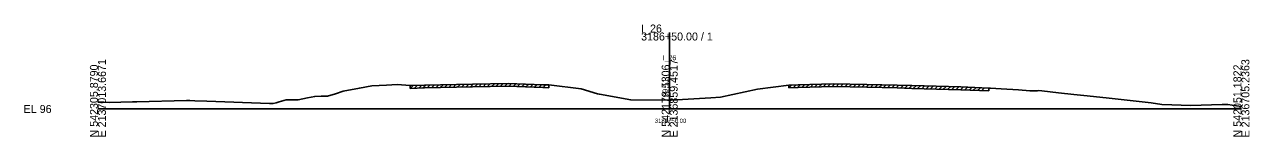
# Model space of a CAD drawing. Extents: x -13101 to 4803, y -924 to 22390.
# Drawn here: x 974.3 to 1402.8, y 12490.3 to 12529.7 of the extents above; entities that cross this region are included whole.
import ezdxf

# ---------------------------------------------------------------- set-up
doc = ezdxf.new("R2010")
doc.units = 0
for name, color, linetype in [('RD_GPK_XS_Cell', 7, 'Continuous'), ('RD_XS_ExGround', 7, 'Continuous'), ('RD_XS_ExPaveRet', 7, 'Continuous'), ('RD_XS_TX_Baseline', 7, 'Continuous'), ('RD_XS_TX_Elev_EX', 7, 'Continuous'), ('RD_XS_TX_Station', 7, 'Continuous')]:
    doc.layers.add(name, color=color, linetype=linetype)

msp = doc.modelspace()

# ---------------------------------------------------------------- linework, layer by layer
at = {"layer": 'RD_GPK_XS_Cell'}
for p, q in [((1200, 12500), (1200, 12526.84)), ((1000, 12500), (1200, 12500)), ((1200, 12500), (1400, 12500))]:
    msp.add_line(p, q, dxfattribs=at)
at = {"layer": 'RD_XS_ExGround'}
msp.add_lwpolyline([(1000, 12502.34), (1002.09, 12502.4), (1003.94, 12502.32), (1012.09, 12502.48), (1013.57, 12502.56), (1030.94, 12502.94), (1032.1, 12502.97), (1033.88, 12502.88), (1038.13, 12502.75), (1060.05, 12501.97), (1061.3, 12501.93), (1062.31, 12502.19), (1063.39, 12502.51), (1065.81, 12503.19), (1067.4, 12503.2), (1070.03, 12503.25), (1073.33, 12503.92), (1075.82, 12504.42), (1078.1, 12504.46), (1080.34, 12504.5), (1083.16, 12505.36), (1085.83, 12506.23), (1091.48, 12507.32), (1095.83, 12508.13), (1100.98, 12508.38), (1104.71, 12508.55), (1109.21, 12508.2), (1114.23, 12508.4), (1131.04, 12508.72), (1143.47, 12508.95), (1155.67, 12508.51), (1157.76, 12508.47), (1169.07, 12507.03), (1174.78, 12505.36), (1175.43, 12505.19), (1186.36, 12503.2), (1200, 12503.11), (1200.48, 12503.11), (1214.43, 12503.91), (1217.8, 12504.18), (1230.77, 12507), (1241.72, 12508.38), (1244.9, 12508.53), (1257.25, 12508.85), (1268.93, 12508.6), (1279.63, 12508.37), (1284.68, 12508.19), (1301.85, 12507.74), (1311.66, 12507.33), (1312.23, 12507.3), (1315.98, 12507.11), (1322.02, 12506.68), (1325.98, 12506.38), (1328.65, 12506.42), (1329.11, 12506.44), (1330.19, 12506.31), (1335.99, 12505.64), (1341.38, 12505.13), (1346, 12504.67), (1353.74, 12503.76), (1362.17, 12502.88), (1368.39, 12502.1), (1372.17, 12501.55), (1375.72, 12501.42), (1382.17, 12501.18), (1393.22, 12501.6), (1395.29, 12501.58), (1398.35, 12501.1), (1400, 12500.9)], dxfattribs=at)
at = {"layer": 'RD_XS_ExPaveRet'}
for p, q in [((1139.21, 12507.87), (1140.23, 12508.89)), ((1140.71, 12507.9), (1141.73, 12508.92)), ((1142.21, 12507.92), (1143.23, 12508.94)), ((1143.71, 12507.94), (1144.68, 12508.9)), ((1109.21, 12507.2), (1110.25, 12508.24)), ((1109.21, 12507.2), (1109.21, 12508.2)), ((1109.21, 12507.2), (1114.23, 12507.4)), ((1110.71, 12507.26), (1111.75, 12508.3)), ((1112.21, 12507.32), (1113.25, 12508.36)), ((1113.71, 12507.38), (1114.74, 12508.41)), ((1114.23, 12507.4), (1131.04, 12507.72)), ((1115.21, 12507.42), (1116.23, 12508.44)), ((1116.71, 12507.45), (1117.73, 12508.47)), ((1118.21, 12507.47), (1119.23, 12508.49)), ((1119.71, 12507.5), (1120.73, 12508.52)), ((1121.21, 12507.53), (1122.23, 12508.55)), ((1122.71, 12507.56), (1123.73, 12508.58)), ((1124.21, 12507.59), (1125.23, 12508.61)), ((1125.71, 12507.62), (1126.73, 12508.64)), ((1127.21, 12507.65), (1128.23, 12508.67)), ((1128.71, 12507.68), (1129.73, 12508.7)), ((1130.21, 12507.71), (1131.23, 12508.73)), ((1131.04, 12507.72), (1143.47, 12507.95)), ((1131.71, 12507.73), (1132.73, 12508.75)), ((1133.21, 12507.76), (1134.23, 12508.78)), ((1134.71, 12507.79), (1135.73, 12508.81)), ((1136.21, 12507.82), (1137.23, 12508.83)), ((1137.71, 12507.84), (1138.73, 12508.86)), ((1143.47, 12507.95), (1155.67, 12507.51)), ((1145.21, 12507.89), (1146.18, 12508.85)), ((1146.71, 12507.83), (1147.68, 12508.8)), ((1148.21, 12507.78), (1149.18, 12508.74)), ((1149.71, 12507.73), (1150.68, 12508.69)), ((1151.21, 12507.67), (1152.18, 12508.64)), ((1152.71, 12507.62), (1153.68, 12508.59)), ((1154.21, 12507.57), (1155.18, 12508.53)), ((1155.67, 12507.51), (1157.76, 12507.47)), ((1155.71, 12507.51), (1156.69, 12508.49)), ((1157.76, 12508.47), (1157.76, 12507.47)), ((1241.72, 12507.38), (1242.77, 12508.43)), ((1241.72, 12507.38), (1241.72, 12508.38)), ((1241.72, 12507.38), (1244.9, 12507.53)), ((1243.22, 12507.45), (1244.27, 12508.5)), ((1244.72, 12507.53), (1245.75, 12508.55)), ((1244.9, 12507.53), (1257.25, 12507.85)), ((1246.22, 12507.57), (1247.25, 12508.59)), ((1247.72, 12507.6), (1248.75, 12508.63)), ((1249.22, 12507.64), (1250.25, 12508.67)), ((1250.72, 12507.68), (1251.75, 12508.71)), ((1252.22, 12507.72), (1253.25, 12508.74)), ((1253.72, 12507.76), (1254.75, 12508.78)), ((1255.22, 12507.79), (1256.25, 12508.82)), ((1256.72, 12507.83), (1257.73, 12508.84)), ((1257.25, 12507.85), (1268.93, 12507.6)), ((1258.22, 12507.83), (1259.2, 12508.8)), ((1259.72, 12507.79), (1260.7, 12508.77)), ((1261.22, 12507.76), (1262.2, 12508.74)), ((1262.72, 12507.73), (1263.7, 12508.71)), ((1264.22, 12507.7), (1265.2, 12508.68)), ((1265.72, 12507.67), (1266.7, 12508.65)), ((1267.22, 12507.63), (1268.2, 12508.61)), ((1268.72, 12507.6), (1269.7, 12508.58)), ((1268.93, 12507.6), (1279.63, 12507.37)), ((1270.22, 12507.57), (1271.2, 12508.55)), ((1271.72, 12507.54), (1272.7, 12508.52)), ((1273.22, 12507.51), (1274.2, 12508.48)), ((1274.72, 12507.47), (1275.7, 12508.45)), ((1276.22, 12507.44), (1277.2, 12508.42)), ((1277.72, 12507.41), (1278.7, 12508.39)), ((1279.22, 12507.37), (1280.19, 12508.35)), ((1279.63, 12507.37), (1284.68, 12507.19)), ((1280.72, 12507.33), (1281.69, 12508.29)), ((1282.22, 12507.27), (1283.19, 12508.24)), ((1283.72, 12507.22), (1284.69, 12508.19)), ((1284.68, 12507.19), (1301.85, 12506.74)), ((1285.22, 12507.17), (1286.2, 12508.15)), ((1286.72, 12507.13), (1287.7, 12508.11)), ((1288.22, 12507.09), (1289.2, 12508.07)), ((1289.72, 12507.05), (1290.7, 12508.03)), ((1291.22, 12507.02), (1292.2, 12507.99)), ((1292.72, 12506.98), (1293.7, 12507.95)), ((1294.22, 12506.94), (1295.2, 12507.91)), ((1295.72, 12506.9), (1296.7, 12507.87)), ((1297.22, 12506.86), (1298.2, 12507.83)), ((1298.72, 12506.82), (1299.7, 12507.79)), ((1300.22, 12506.78), (1301.2, 12507.75)), ((1301.72, 12506.74), (1302.68, 12507.7)), ((1301.85, 12506.74), (1311.66, 12506.33)), ((1303.22, 12506.68), (1304.18, 12507.64)), ((1304.72, 12506.62), (1305.68, 12507.58)), ((1306.22, 12506.55), (1307.18, 12507.51)), ((1307.72, 12506.49), (1308.68, 12507.45)), ((1309.22, 12506.43), (1310.18, 12507.39)), ((1311.66, 12507.33), (1311.66, 12506.33))]:
    msp.add_line(p, q, dxfattribs=at)

# ---------------------------------------------------------------- texts
at = {"layer": 'RD_GPK_XS_Cell'}
for s, p in [('3186+50.00 / 1', (1190, 12524.04)), ('I_26', (1190, 12526.84)), ('EL 96', (974, 12498.6))]:
    msp.add_text(s, height=2.8, dxfattribs=at).set_placement(p)
for s, p in [('N 542305.8790', (1000, 12490)), ('E 2137013.6671', (1002.8, 12490)), ('N 542178.5306', (1200, 12490)), ('E 2136859.4517', (1202.8, 12490)), ('N 542051.1822', (1400, 12490)), ('E 2136705.2363', (1402.8, 12490))]:
    msp.add_text(s, height=2.8, rotation=90, dxfattribs=at).set_placement(p)
at = {"layer": 'RD_XS_TX_Baseline'}
msp.add_text('I_26', height=1.75, dxfattribs=at).set_placement((1197.6, 12517.11))
at = {"layer": 'RD_XS_TX_Elev_EX'}
msp.add_text('99.11', height=2, rotation=90, dxfattribs=at).set_placement((1199.5, 12504.11))
at = {"layer": 'RD_XS_TX_Station'}
msp.add_text('3186+50.00', height=1.5, dxfattribs=at).set_placement((1194.81, 12495.11))

doc.saveas('drawing.dxf')
